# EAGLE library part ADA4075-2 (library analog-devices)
Ultralow Noise Amplifier at Lower Power Source: http://www.analog.com/static/imported-files/data_sheets/ADA4075-2.pdf
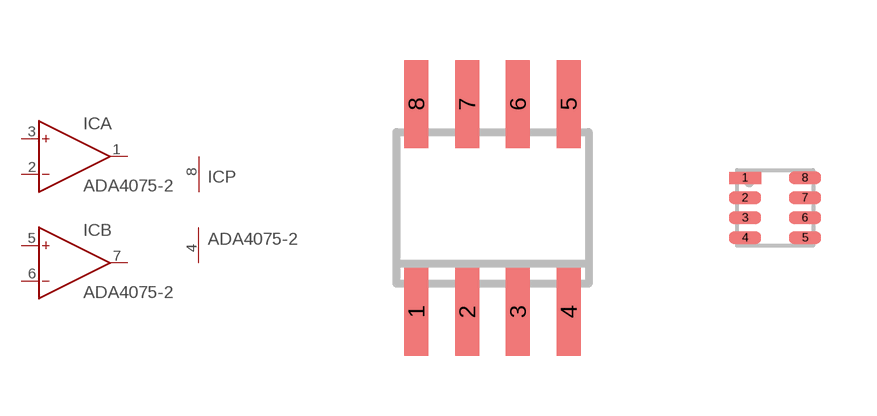
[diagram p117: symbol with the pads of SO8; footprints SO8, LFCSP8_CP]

Designator prefix IC; gates A=OP B=OP P=PWR+-

## ADA4075-2R (MPN: ADA4075-2ARZ; OC_FARNELL: 1701254; OC_NEWARK: 19P8164)  [SO8]
1  A:OUT  out
2  A:IN-  in
3  A:IN+  in
4  P:V-  pwr
5  B:IN+  in
6  B:IN-  in
7  B:OUT  out
8  P:V+  pwr

## ADA4075-2CP (MPN: ADA4075-2ACPZ-R7; OC_FARNELL: unknown; OC_NEWARK: 26R2389)  [LFCSP8_CP]
Pads as for SO8

## Footprint SO8 (pad centres in mm)
8-Lead Small Outline IC (SO-8) Source: http://www.analog.com/UploadedFiles/Data_Sheets/703465986AD8611_2_0.pdf
smd 0.6 x 2.2: 1 -1.905,-2.6; 2 -0.635,-2.6; 3 0.635,-2.6; 4 1.905,-2.6; 5 1.905,2.6; 6 0.635,2.6; 7 -0.635,2.6; 8 -1.905,2.6

## Footprint LFCSP8_CP (pad centres in mm)
8-Lead Lead Frame Chip Scale Package LFCSP_WD 2 mm × 2 mm Body, Very Very Thin, Dual Lead Source: http://www.analog.com/static/imported-files/data_sheets/ADA4075-2.pdf
smd 0.8 x 0.3: 1 -0.75,0.75; 2 -0.75,0.25; 3 -0.75,-0.25; 4 -0.75,-0.75; 5 0.75,-0.75; 6 0.75,-0.25; 7 0.75,0.25; 8 0.75,0.75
